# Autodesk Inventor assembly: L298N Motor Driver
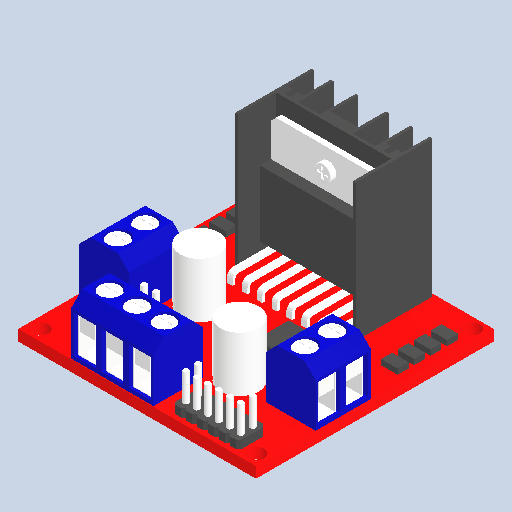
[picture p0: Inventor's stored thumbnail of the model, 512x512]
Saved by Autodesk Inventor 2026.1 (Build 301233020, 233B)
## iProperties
Created: 2025-07
Part Number: L298N Motor Driver
Document SubType Name: Assembly
Designer: hp
Sending System: Autodesk Translation Framework v14.10.0.0
Preprocessor: ST-DEVELOPER v20.1
Title: L298N Motor Driver.step
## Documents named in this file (4)
- C:\Users\hp\Documents\Inventor\DOM1_CartesianRobot\L298N Motor Driver.iam
- C:\Users\hp\Downloads\L298N Motor Driver\L298N Motor Driver\Pcb.ipt
- C:\Users\hp\Downloads\L298N Motor Driver\L298N Motor Driver\Pengunci.ipt
- C:\Users\hp\Downloads\L298N Motor Driver\L298N Motor Driver\Pengunci 2.ipt
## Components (4 placed, 3 different names)
1. Pcb:1
2. Pengunci:1
3. Pengunci 2:1
4. Pengunci:2
